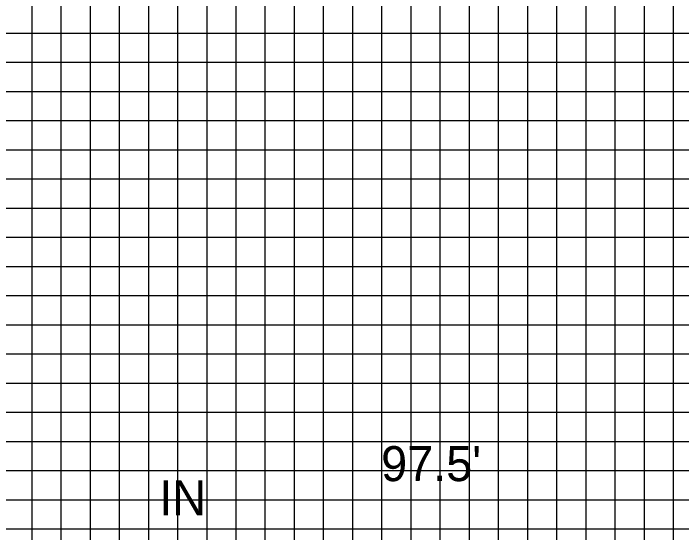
# Model space of a CAD drawing. Extents: x 1758647 to 1758990, y 442323 to 442543.
# Drawn here: x 1758895.78 to 1758918.7, y 442366.76 to 442384.56 of the extents above; entities that cross this region are included whole.
import ezdxf

# ---------------------------------------------------------------- set-up
doc = ezdxf.new("R2010")
doc.units = 0
for name, color, linetype in [('ANNOTATION', 7, 'Continuous'), ('MAJOR', 7, 'Continuous'), ('MINOR', 7, 'Continuous')]:
    doc.layers.add(name, color=color, linetype=linetype)

msp = doc.modelspace()

# ---------------------------------------------------------------- linework, layer by layer
at = {"layer": 'MAJOR'}
for p, q in [((1758902.422, 442348.886), (1758902.422, 442388.886)), ((1758912.422, 442348.886), (1758912.422, 442388.886)), ((1758672.422, 442383.886), (1758952.422, 442383.886)), ((1758672.422, 442378.886), (1758952.422, 442378.886)), ((1758672.422, 442373.886), (1758952.422, 442373.886)), ((1758672.422, 442368.886), (1758952.422, 442368.886))]:
    msp.add_line(p, q, dxfattribs=at)
at = {"layer": 'MINOR'}
for p, q in [((1758896.422, 442348.886), (1758896.422, 442388.886)), ((1758897.422, 442348.886), (1758897.422, 442388.886)), ((1758898.422, 442348.886), (1758898.422, 442388.886)), ((1758899.422, 442348.886), (1758899.422, 442388.886)), ((1758900.422, 442348.886), (1758900.422, 442388.886)), ((1758901.422, 442348.886), (1758901.422, 442388.886)), ((1758903.422, 442348.886), (1758903.422, 442388.886)), ((1758904.422, 442348.886), (1758904.422, 442388.886)), ((1758905.422, 442348.886), (1758905.422, 442388.886)), ((1758906.422, 442348.886), (1758906.422, 442388.886)), ((1758907.422, 442348.886), (1758907.422, 442388.886)), ((1758908.422, 442348.886), (1758908.422, 442388.886)), ((1758909.422, 442348.886), (1758909.422, 442388.886)), ((1758910.422, 442348.886), (1758910.422, 442388.886)), ((1758911.422, 442348.886), (1758911.422, 442388.886)), ((1758913.422, 442348.886), (1758913.422, 442388.886)), ((1758914.422, 442348.886), (1758914.422, 442388.886)), ((1758915.422, 442348.886), (1758915.422, 442388.886)), ((1758916.422, 442348.886), (1758916.422, 442388.886)), ((1758917.422, 442348.886), (1758917.422, 442388.886)), ((1758918.422, 442348.886), (1758918.422, 442388.886)), ((1758672.422, 442382.886), (1758952.422, 442382.886)), ((1758672.422, 442381.886), (1758952.422, 442381.886)), ((1758672.422, 442380.886), (1758952.422, 442380.886)), ((1758672.422, 442379.886), (1758952.422, 442379.886)), ((1758672.422, 442377.886), (1758952.422, 442377.886)), ((1758672.422, 442376.886), (1758952.422, 442376.886)), ((1758672.422, 442375.886), (1758952.422, 442375.886)), ((1758672.422, 442374.886), (1758952.422, 442374.886)), ((1758672.422, 442372.886), (1758952.422, 442372.886)), ((1758672.422, 442371.886), (1758952.422, 442371.886)), ((1758672.422, 442370.886), (1758952.422, 442370.886)), ((1758672.422, 442369.886), (1758952.422, 442369.886)), ((1758672.422, 442367.886), (1758952.422, 442367.886)), ((1758672.422, 442366.886), (1758952.422, 442366.886))]:
    msp.add_line(p, q, dxfattribs=at)

# ---------------------------------------------------------------- texts
at = {"layer": 'ANNOTATION'}
for s, p in [("97.5'", (1758908.394, 442368.523)), ('IN', (1758900.782, 442367.355))]:
    msp.add_text(s, height=1.2, dxfattribs=at).set_placement(p)

doc.saveas('drawing.dxf')
